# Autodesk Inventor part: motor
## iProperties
Created: 2007-01
Part Number: motor
Document SubType Name: Modeling
Density: 1 g/cm^3
Stock Number: motor
GlobalPropertyList: <PropertyList/>
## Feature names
1. Extrusion1
2. Fillet1
3. Extrusion2
4. Extrusion3
5. Fillet2
6. Extrusion4
7. Fillet3
8. Extrusion5
9. Extrusion6
10. Fillet4
11. Extrusion7
12. Circular Pattern1
13. Extrusion8
14. Extrusion9
15. Chamfer1
16. Extrusion10
17. Circular Pattern2
